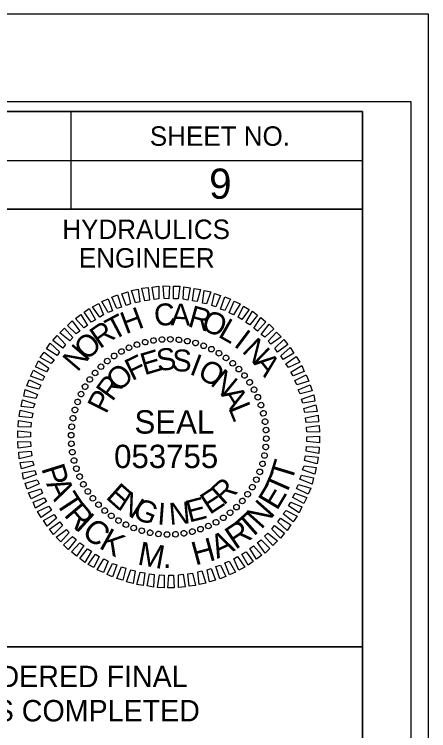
# Model space of a CAD drawing. Extents: x 1632687 to 1634895, y 1174336 to 1175436.
# Drawn here: x 1634264.8 to 1634371.3, y 1175251.7 to 1175435.8 of the extents above; entities that cross this region are included whole.
import ezdxf

# ---------------------------------------------------------------- set-up
doc = ezdxf.new("R2010")
doc.units = 0
for name, color, linetype in [('Sheet Data Field CELL', 7, 'Continuous'), ('Sheet PE Seal Cell', 7, 'Continuous'), ('Sheet Plot Border Inside CELL', 7, 'Continuous'), ('Sheet Plot Border Outside CELL', 7, 'Continuous'), ('Sheet Profile CELL', 7, 'Continuous'), ('Sheet Profile Grid Major CELL', 7, 'Continuous'), ('Sheet Sticker Exception Certification CELL', 7, 'Continuous')]:
    doc.layers.add(name, color=color, linetype=linetype)

msp = doc.modelspace()

# ---------------------------------------------------------------- linework, layer by layer
at = {"layer": 'Sheet PE Seal Cell'}
for p, q in [((1634302.73, 1175352.25), (1634302.73, 1175352.25)), ((1634304.93, 1175352.3), (1634304.93, 1175352.3)), ((1634296.28, 1175350.95), (1634296.28, 1175350.95)), ((1634298.38, 1175351.55), (1634298.38, 1175351.55)), ((1634300.58, 1175351.95), (1634300.58, 1175351.95)), ((1634307.13, 1175352.15), (1634307.13, 1175352.15)), ((1634309.28, 1175351.8), (1634309.28, 1175351.8)), ((1634311.38, 1175351.35), (1634311.38, 1175351.35)), ((1634313.48, 1175350.65), (1634313.48, 1175350.65)), ((1634292.33, 1175349.15), (1634292.33, 1175349.15)), ((1634294.28, 1175350.15), (1634294.28, 1175350.15)), ((1634315.48, 1175349.75), (1634315.48, 1175349.75)), ((1634317.43, 1175348.75), (1634317.43, 1175348.75)), ((1634288.68, 1175346.75), (1634288.68, 1175346.75)), ((1634290.43, 1175348), (1634290.43, 1175348)), ((1634319.23, 1175347.5), (1634319.23, 1175347.5)), ((1634287.03, 1175345.25), (1634287.03, 1175345.25)), ((1634320.98, 1175346.15), (1634320.98, 1175346.15)), ((1634285.53, 1175343.7), (1634285.53, 1175343.7)), ((1634322.53, 1175344.65), (1634322.53, 1175344.65)), ((1634284.18, 1175341.95), (1634284.18, 1175341.95)), ((1634324.03, 1175343), (1634324.03, 1175343)), ((1634325.28, 1175341.25), (1634325.28, 1175341.25)), ((1634282.93, 1175340.15), (1634282.93, 1175340.15)), ((1634281.93, 1175338.2), (1634281.93, 1175338.2)), ((1634326.43, 1175339.35), (1634326.43, 1175339.35)), ((1634281.03, 1175336.2), (1634281.03, 1175336.2)), ((1634327.43, 1175337.4), (1634327.43, 1175337.4)), ((1634280.33, 1175334.1), (1634280.33, 1175334.1)), ((1634328.23, 1175335.4), (1634328.23, 1175335.4)), ((1634279.88, 1175332), (1634279.88, 1175332)), ((1634328.83, 1175333.3), (1634328.83, 1175333.3)), ((1634329.23, 1175331.1), (1634329.23, 1175331.1)), ((1634279.53, 1175329.85), (1634279.53, 1175329.85)), ((1634329.53, 1175328.95), (1634329.53, 1175328.95)), ((1634279.38, 1175327.65), (1634279.38, 1175327.65)), ((1634304.48, 1175327.2), (1634304.48, 1175327.2)), ((1634329.58, 1175326.75), (1634329.58, 1175326.75)), ((1634279.43, 1175325.45), (1634279.43, 1175325.45)), ((1634279.73, 1175323.3), (1634279.73, 1175323.3)), ((1634329.43, 1175324.55), (1634329.43, 1175324.55)), ((1634280.13, 1175321.1), (1634280.13, 1175321.1)), ((1634329.08, 1175322.4), (1634329.08, 1175322.4)), ((1634328.63, 1175320.3), (1634328.63, 1175320.3)), ((1634280.73, 1175319), (1634280.73, 1175319)), ((1634327.93, 1175318.2), (1634327.93, 1175318.2)), ((1634281.53, 1175317), (1634281.53, 1175317)), ((1634327.03, 1175316.2), (1634327.03, 1175316.2)), ((1634282.53, 1175315.05), (1634282.53, 1175315.05)), ((1634326.03, 1175314.25), (1634326.03, 1175314.25)), ((1634283.68, 1175313.15), (1634283.68, 1175313.15)), ((1634324.78, 1175312.45), (1634324.78, 1175312.45)), ((1634284.93, 1175311.4), (1634284.93, 1175311.4)), ((1634323.43, 1175310.7), (1634323.43, 1175310.7)), ((1634286.43, 1175309.75), (1634286.43, 1175309.75)), ((1634287.98, 1175308.25), (1634287.98, 1175308.25)), ((1634321.93, 1175309.15), (1634321.93, 1175309.15)), ((1634289.73, 1175306.9), (1634289.73, 1175306.9)), ((1634318.53, 1175306.4), (1634318.53, 1175306.4)), ((1634320.28, 1175307.65), (1634320.28, 1175307.65)), ((1634291.53, 1175305.65), (1634291.53, 1175305.65)), ((1634293.48, 1175304.65), (1634293.48, 1175304.65)), ((1634316.63, 1175305.25), (1634316.63, 1175305.25)), ((1634295.48, 1175303.75), (1634295.48, 1175303.75)), ((1634297.58, 1175303.05), (1634297.58, 1175303.05)), ((1634299.68, 1175302.6), (1634299.68, 1175302.6)), ((1634310.58, 1175302.85), (1634310.58, 1175302.85)), ((1634312.68, 1175303.45), (1634312.68, 1175303.45)), ((1634314.68, 1175304.25), (1634314.68, 1175304.25)), ((1634301.83, 1175302.25), (1634301.83, 1175302.25)), ((1634304.03, 1175302.1), (1634304.03, 1175302.1)), ((1634306.23, 1175302.15), (1634306.23, 1175302.15)), ((1634308.38, 1175302.45), (1634308.38, 1175302.45))]:
    msp.add_line(p, q, dxfattribs=at)
for points in [[(1634295.98, 1175361.65), (1634294.93, 1175364.8), (1634296.63, 1175365.15), (1634297.03, 1175361.9)], [(1634298.38, 1175362.2), (1634297.58, 1175365.4), (1634299.23, 1175365.55), (1634299.58, 1175362.35)], [(1634300.78, 1175362.5), (1634300.23, 1175365.7), (1634301.93, 1175365.9), (1634301.98, 1175362.65)], [(1634303.28, 1175362.75), (1634303.03, 1175366), (1634304.68, 1175365.95), (1634304.48, 1175362.7)], [(1634305.68, 1175362.7), (1634305.68, 1175365.95), (1634307.33, 1175365.9), (1634306.88, 1175362.65)], [(1634308.18, 1175362.55), (1634308.38, 1175365.8), (1634310.03, 1175365.5), (1634309.38, 1175362.35)], [(1634310.58, 1175362.15), (1634311.03, 1175365.35), (1634312.68, 1175365.1), (1634311.78, 1175362)], [(1634291.13, 1175360.2), (1634289.83, 1175363.1), (1634291.33, 1175363.7), (1634292.38, 1175360.5)], [(1634293.58, 1175361), (1634292.43, 1175364), (1634293.98, 1175364.45), (1634294.63, 1175361.35)], [(1634313.13, 1175361.6), (1634313.63, 1175364.85), (1634315.33, 1175364.45), (1634314.18, 1175361.35)], [(1634315.53, 1175360.95), (1634316.28, 1175364.05), (1634317.83, 1175363.55), (1634316.58, 1175360.6)], [(1634286.78, 1175357.95), (1634284.93, 1175360.65), (1634286.48, 1175361.45), (1634287.73, 1175358.55)], [(1634288.93, 1175359.15), (1634287.33, 1175361.95), (1634288.88, 1175362.65), (1634290.03, 1175359.6)], [(1634317.78, 1175360.05), (1634318.93, 1175363.2), (1634320.33, 1175362.6), (1634318.93, 1175359.7)], [(1634320.03, 1175359.1), (1634321.28, 1175362.05), (1634322.83, 1175361.35), (1634321.13, 1175358.55)], [(1634284.58, 1175356.7), (1634282.73, 1175359.25), (1634284.03, 1175360.2), (1634285.68, 1175357.3)], [(1634322.33, 1175357.95), (1634323.68, 1175360.8), (1634325.18, 1175359.95), (1634323.28, 1175357.35)], [(1634282.68, 1175355.2), (1634280.53, 1175357.6), (1634281.88, 1175358.65), (1634283.63, 1175355.85)], [(1634324.28, 1175356.6), (1634326.03, 1175359.5), (1634327.33, 1175358.45), (1634325.38, 1175356)], [(1634326.33, 1175355.1), (1634328.18, 1175357.85), (1634329.48, 1175356.75), (1634327.28, 1175354.4)], [(1634280.68, 1175353.65), (1634278.48, 1175355.85), (1634279.68, 1175357.05), (1634281.63, 1175354.35)], [(1634328.23, 1175353.55), (1634330.28, 1175356.15), (1634331.48, 1175354.95), (1634329.18, 1175352.8)], [(1634279.03, 1175351.9), (1634276.48, 1175353.95), (1634277.73, 1175355.1), (1634279.83, 1175352.7)], [(1634330.03, 1175351.8), (1634332.18, 1175354.15), (1634333.38, 1175352.95), (1634330.78, 1175351)], [(1634277.28, 1175350), (1634274.68, 1175351.95), (1634275.78, 1175353.25), (1634277.98, 1175350.9)], [(1634331.78, 1175350), (1634334.08, 1175352.25), (1634335.13, 1175350.9), (1634332.48, 1175349)], [(1634275.78, 1175348.1), (1634273.08, 1175349.8), (1634274.03, 1175351.25), (1634276.43, 1175349.05)], [(1634274.28, 1175346.1), (1634271.48, 1175347.6), (1634272.48, 1175349), (1634275.08, 1175347)], [(1634333.28, 1175348.05), (1634335.73, 1175350.15), (1634336.68, 1175348.7), (1634333.88, 1175347.1)], [(1634273.08, 1175343.95), (1634270.23, 1175345.2), (1634270.98, 1175346.75), (1634273.68, 1175344.9)], [(1634334.58, 1175346), (1634337.23, 1175347.9), (1634338.18, 1175346.4), (1634335.28, 1175345)], [(1634335.88, 1175343.8), (1634338.68, 1175345.55), (1634339.33, 1175344), (1634336.48, 1175342.85)], [(1634272.08, 1175341.65), (1634268.98, 1175342.8), (1634269.73, 1175344.35), (1634272.58, 1175342.75)], [(1634336.88, 1175341.65), (1634339.83, 1175343.15), (1634340.48, 1175341.55), (1634337.38, 1175340.55)], [(1634271.08, 1175339.45), (1634267.98, 1175340.35), (1634268.63, 1175341.9), (1634271.63, 1175340.5)], [(1634337.78, 1175339.3), (1634340.83, 1175340.6), (1634341.38, 1175339.05), (1634338.28, 1175338.25)], [(1634270.33, 1175337.05), (1634267.23, 1175337.7), (1634267.58, 1175339.35), (1634270.73, 1175338.1)], [(1634338.58, 1175336.9), (1634341.78, 1175338.05), (1634342.08, 1175336.4), (1634338.93, 1175335.85)], [(1634269.68, 1175334.65), (1634266.58, 1175335.05), (1634266.93, 1175336.75), (1634270.08, 1175335.7)], [(1634269.28, 1175332.1), (1634266.08, 1175332.4), (1634266.28, 1175334.1), (1634269.53, 1175333.3)], [(1634339.18, 1175334.5), (1634342.33, 1175335.45), (1634342.63, 1175333.75), (1634339.48, 1175333.45)], [(1634339.63, 1175332.1), (1634342.88, 1175332.8), (1634343.03, 1175331.1), (1634339.83, 1175330.9)], [(1634269.03, 1175329.7), (1634265.78, 1175329.8), (1634265.88, 1175331.45), (1634269.13, 1175330.9)], [(1634268.98, 1175327.2), (1634265.73, 1175327.05), (1634265.73, 1175328.75), (1634268.98, 1175328.4)], [(1634339.93, 1175329.7), (1634343.18, 1175330.1), (1634343.28, 1175328.4), (1634340.03, 1175328.5)], [(1634339.98, 1175327.2), (1634343.23, 1175327.35), (1634343.23, 1175325.65), (1634339.98, 1175326)], [(1634269.03, 1175324.7), (1634265.78, 1175324.3), (1634265.68, 1175326), (1634268.93, 1175325.9)], [(1634339.93, 1175324.7), (1634343.18, 1175324.6), (1634343.08, 1175322.95), (1634339.83, 1175323.5)], [(1634269.33, 1175322.3), (1634266.08, 1175321.6), (1634265.93, 1175323.3), (1634269.13, 1175323.5)], [(1634269.78, 1175319.9), (1634266.63, 1175318.95), (1634266.33, 1175320.65), (1634269.48, 1175320.95)], [(1634339.68, 1175322.3), (1634342.88, 1175322), (1634342.68, 1175320.3), (1634339.43, 1175321.1)], [(1634339.28, 1175319.75), (1634342.38, 1175319.35), (1634342.03, 1175317.65), (1634338.88, 1175318.7)], [(1634270.38, 1175317.5), (1634267.18, 1175316.35), (1634266.88, 1175318), (1634270.03, 1175318.55)], [(1634338.63, 1175317.35), (1634341.73, 1175316.7), (1634341.38, 1175315.05), (1634338.23, 1175316.3)], [(1634271.18, 1175315.1), (1634268.13, 1175313.8), (1634267.58, 1175315.35), (1634270.68, 1175316.15)], [(1634272.08, 1175312.75), (1634269.13, 1175311.25), (1634268.48, 1175312.85), (1634271.58, 1175313.85)], [(1634337.88, 1175314.95), (1634340.98, 1175314.05), (1634340.33, 1175312.5), (1634337.33, 1175313.9)], [(1634336.88, 1175312.75), (1634339.98, 1175311.6), (1634339.23, 1175310.05), (1634336.38, 1175311.65)], [(1634273.08, 1175310.6), (1634270.28, 1175308.85), (1634269.63, 1175310.4), (1634272.48, 1175311.55)], [(1634335.88, 1175310.45), (1634338.73, 1175309.2), (1634337.98, 1175307.65), (1634335.28, 1175309.5)], [(1634274.38, 1175308.4), (1634271.73, 1175306.5), (1634270.78, 1175308), (1634273.68, 1175309.4)], [(1634334.68, 1175308.3), (1634337.48, 1175306.8), (1634336.48, 1175305.4), (1634333.88, 1175307.4)], [(1634275.68, 1175306.35), (1634273.23, 1175304.25), (1634272.28, 1175305.7), (1634275.08, 1175307.3)], [(1634333.18, 1175306.3), (1634335.88, 1175304.6), (1634334.93, 1175303.15), (1634332.53, 1175305.35)], [(1634277.18, 1175304.4), (1634274.88, 1175302.15), (1634273.83, 1175303.5), (1634276.48, 1175305.4)], [(1634331.68, 1175304.4), (1634334.28, 1175302.45), (1634333.18, 1175301.15), (1634330.98, 1175303.5)], [(1634278.93, 1175302.6), (1634276.78, 1175300.25), (1634275.58, 1175301.45), (1634278.18, 1175303.4)], [(1634280.73, 1175300.85), (1634278.68, 1175298.25), (1634277.48, 1175299.45), (1634279.78, 1175301.6)], [(1634328.28, 1175300.75), (1634330.48, 1175298.55), (1634329.28, 1175297.35), (1634327.33, 1175300.05)], [(1634329.93, 1175302.5), (1634332.48, 1175300.45), (1634331.23, 1175299.3), (1634329.13, 1175301.7)], [(1634282.63, 1175299.3), (1634280.78, 1175296.55), (1634279.48, 1175297.65), (1634281.68, 1175300)], [(1634326.28, 1175299.2), (1634328.43, 1175296.8), (1634327.08, 1175295.75), (1634325.33, 1175298.55)], [(1634284.68, 1175297.8), (1634282.93, 1175294.9), (1634281.63, 1175295.95), (1634283.58, 1175298.4)], [(1634286.63, 1175296.45), (1634285.28, 1175293.6), (1634283.78, 1175294.45), (1634285.68, 1175297.05)], [(1634324.38, 1175297.7), (1634326.23, 1175295.15), (1634324.93, 1175294.2), (1634323.28, 1175297.1)], [(1634288.93, 1175295.3), (1634287.68, 1175292.35), (1634286.13, 1175293.05), (1634287.83, 1175295.85)], [(1634320.03, 1175295.25), (1634321.63, 1175292.45), (1634320.08, 1175291.75), (1634318.93, 1175294.8)], [(1634322.18, 1175296.45), (1634324.03, 1175293.75), (1634322.48, 1175292.95), (1634321.23, 1175295.85)], [(1634291.18, 1175294.35), (1634290.03, 1175291.2), (1634288.63, 1175291.8), (1634290.03, 1175294.7)], [(1634293.43, 1175293.45), (1634292.68, 1175290.35), (1634291.13, 1175290.85), (1634292.38, 1175293.8)], [(1634315.38, 1175293.4), (1634316.53, 1175290.4), (1634314.98, 1175289.95), (1634314.33, 1175293.05)], [(1634317.83, 1175294.2), (1634319.13, 1175291.3), (1634317.63, 1175290.7), (1634316.58, 1175293.9)], [(1634295.83, 1175292.8), (1634295.33, 1175289.55), (1634293.63, 1175289.95), (1634294.78, 1175293.05)], [(1634298.38, 1175292.25), (1634297.93, 1175289.05), (1634296.28, 1175289.3), (1634297.18, 1175292.4)], [(1634300.78, 1175291.85), (1634300.58, 1175288.6), (1634298.93, 1175288.9), (1634299.58, 1175292.05)], [(1634303.28, 1175291.7), (1634303.28, 1175288.45), (1634301.63, 1175288.5), (1634302.08, 1175291.75)], [(1634305.68, 1175291.65), (1634305.93, 1175288.4), (1634304.28, 1175288.45), (1634304.48, 1175291.7)], [(1634308.18, 1175291.9), (1634308.73, 1175288.7), (1634307.03, 1175288.5), (1634306.98, 1175291.75)], [(1634310.58, 1175292.2), (1634311.38, 1175289), (1634309.73, 1175288.85), (1634309.38, 1175292.05)], [(1634312.98, 1175292.75), (1634314.03, 1175289.6), (1634312.33, 1175289.25), (1634311.93, 1175292.5)]]:
    msp.add_lwpolyline(points, close=True, dxfattribs=at)
for centre, major_axis in [((1634298.42, 1175351.53), (-0.174, 0.699)), ((1634300.56, 1175351.97), (-0.113, 0.711)), ((1634302.73, 1175352.22), (-0.05, 0.718)), ((1634304.92, 1175352.28), (0.013, 0.72)), ((1634307.11, 1175352.14), (0.075, 0.716)), ((1634309.27, 1175351.82), (0.137, 0.707)), ((1634294.28, 1175350.11), (-0.293, 0.658)), ((1634296.32, 1175350.91), (-0.234, 0.681)), ((1634311.4, 1175351.31), (0.198, 0.692)), ((1634313.47, 1175350.61), (0.258, 0.672)), ((1634315.48, 1175349.74), (0.316, 0.647)), ((1634290.46, 1175347.99), (-0.403, 0.597)), ((1634292.33, 1175349.14), (-0.349, 0.63)), ((1634317.4, 1175348.7), (0.371, 0.617)), ((1634288.7, 1175346.69), (-0.453, 0.56)), ((1634319.23, 1175347.49), (0.423, 0.582)), ((1634320.94, 1175346.13), (0.472, 0.543)), ((1634287.06, 1175345.24), (-0.5, 0.518)), ((1634322.53, 1175344.62), (0.518, 0.5)), ((1634285.56, 1175343.65), (-0.543, 0.472)), ((1634323.98, 1175342.98), (0.56, 0.453)), ((1634284.19, 1175341.94), (-0.582, 0.423)), ((1634325.28, 1175341.22), (0.597, 0.403)), ((1634282.99, 1175340.12), (-0.617, 0.371)), ((1634326.42, 1175339.36), (0.63, 0.349)), ((1634281.94, 1175338.19), (-0.647, 0.316)), ((1634327.4, 1175337.4), (0.658, 0.293)), ((1634281.07, 1175336.19), (-0.672, 0.258)), ((1634328.2, 1175335.37), (0.681, 0.234)), ((1634280.38, 1175334.11), (-0.692, 0.198)), ((1634328.82, 1175333.27), (0.699, 0.174)), ((1634279.87, 1175331.99), (-0.707, 0.137)), ((1634279.54, 1175329.82), (-0.716, 0.075)), ((1634329.26, 1175331.12), (0.711, 0.113)), ((1634279.41, 1175327.64), (-0.72, 0.013)), ((1634329.5, 1175328.95), (0.718, 0.05)), ((1634329.56, 1175326.76), (0.72, -0.013)), ((1634279.47, 1175325.45), (-0.718, -0.05)), ((1634329.43, 1175324.58), (0.716, -0.075)), ((1634279.71, 1175323.28), (-0.711, -0.113)), ((1634329.1, 1175322.41), (0.707, -0.137)), ((1634280.15, 1175321.13), (-0.699, -0.174)), ((1634328.59, 1175320.29), (0.692, -0.198)), ((1634280.77, 1175319.03), (-0.681, -0.234)), ((1634281.57, 1175317), (-0.658, -0.293)), ((1634327.9, 1175318.21), (0.672, -0.258)), ((1634282.55, 1175315.04), (-0.63, -0.349)), ((1634327.03, 1175316.21), (0.647, -0.316)), ((1634283.69, 1175313.18), (-0.597, -0.403)), ((1634325.98, 1175314.28), (0.617, -0.371)), ((1634284.99, 1175311.42), (-0.56, -0.453)), ((1634324.77, 1175312.46), (0.582, -0.423)), ((1634286.44, 1175309.78), (-0.518, -0.5)), ((1634321.91, 1175309.16), (0.5, -0.518)), ((1634323.41, 1175310.75), (0.543, -0.472)), ((1634288.03, 1175308.27), (-0.472, -0.543)), ((1634320.27, 1175307.71), (0.453, -0.56)), ((1634289.74, 1175306.91), (-0.423, -0.582)), ((1634291.57, 1175305.7), (-0.371, -0.617)), ((1634318.51, 1175306.41), (0.403, -0.597)), ((1634293.49, 1175304.66), (-0.316, -0.647)), ((1634295.5, 1175303.79), (-0.258, -0.672)), ((1634314.69, 1175304.29), (0.293, -0.658)), ((1634316.64, 1175305.26), (0.349, -0.63)), ((1634297.57, 1175303.09), (-0.198, -0.692)), ((1634299.7, 1175302.58), (-0.137, -0.707)), ((1634301.86, 1175302.26), (-0.075, -0.716)), ((1634304.05, 1175302.12), (-0.013, -0.72)), ((1634306.23, 1175302.18), (0.05, -0.718)), ((1634308.41, 1175302.43), (0.113, -0.711)), ((1634310.55, 1175302.86), (0.174, -0.699)), ((1634312.65, 1175303.49), (0.234, -0.681))]:
    msp.add_ellipse(centre, major_axis=major_axis, ratio=0.999708, dxfattribs=at)
at = {"layer": 'Sheet Plot Border Inside CELL'}
msp.add_lwpolyline([(1632700.31, 1174358.24), (1634366.81, 1174358.24), (1634366.81, 1175413.34), (1632700.31, 1175413.34)], close=True, dxfattribs=at)
at = {"layer": 'Sheet Plot Border Outside CELL'}
msp.add_lwpolyline([(1632687.31, 1174335.79), (1634371.31, 1174335.79), (1634371.31, 1175435.79), (1632687.31, 1175435.79)], close=True, dxfattribs=at)
at = {"layer": 'Sheet Profile CELL'}
for p, q in [((1634279.31, 1175410.74), (1634279.31, 1175385.74)), ((1634154.26, 1175398.24), (1634354.31, 1175398.24))]:
    msp.add_line(p, q, dxfattribs=at)
for points in [[(1634354.31, 1175410.79), (1632854.31, 1175410.79), (1632854.31, 1174360.79), (1634354.31, 1174360.79)], [(1634154.26, 1175410.79), (1634354.31, 1175410.79), (1634354.31, 1175385.74), (1634154.26, 1175385.74)], [(1634254.31, 1175385.74), (1634354.31, 1175385.74), (1634354.31, 1175273.24), (1634254.31, 1175273.24)]]:
    msp.add_lwpolyline(points, close=True, dxfattribs=at)
at = {"layer": 'Sheet Profile Grid Major CELL'}
msp.add_lwpolyline([(1634304.31, 1175249.74), (1634304.31, 1174910.79), (1634354.31, 1174910.79), (1634354.31, 1175260.79)], dxfattribs=at)
at = {"layer": 'Sheet Sticker Exception Certification CELL'}
for p, q in [((1634154.26, 1175273.24), (1634354.3, 1175273.24)), ((1634354.3, 1175273.22), (1634354.3, 1175249.72))]:
    msp.add_line(p, q, dxfattribs=at)

# ---------------------------------------------------------------- texts
at = {"layer": 'Sheet Data Field CELL'}
msp.add_text('9', height=7.75, rotation=360, dxfattribs=at).set_placement((1634314.88, 1175388.4))
at = {"layer": 'Sheet PE Seal Cell'}
for s, height, rotation, p in [('C', 5.64, 6.2199, (1634301.03, 1175355.55)), ('A', 5.64, 359.0203, (1634304.98, 1175355.85)), ('H', 5.64, 20.6195, (1634293.43, 1175353.55)), ('R', 5.64, 344.6211, (1634309.18, 1175355.65)), ('T', 5.64, 27.8198, (1634290.18, 1175351.9)), ('O', 5.64, 337.4212, (1634312.53, 1175354.9)), ('R', 5.64, 35.0205, (1634286.78, 1175349.7)), ('L', 5.64, 330.2209, (1634316.93, 1175353.05)), ('I', 5.64, 323.0201, (1634320.98, 1175350.65)), ('O', 5.64, 42.2217, (1634283.33, 1175346.6)), ('N', 5.64, 315.8189, (1634323.13, 1175349.1)), ('N', 5.64, 49.4235, (1634281.03, 1175343.7)), ('E', 5.64, 16.6111, (1634298.23, 1175343)), ('S', 5.64, 7.2556, (1634301.68, 1175344.05)), ('S', 5.64, 357.9004, (1634305.28, 1175344.1)), ('F', 5.64, 25.967, (1634295.03, 1175341.5)), ('I', 5.64, 339.1896, (1634309.58, 1175343.4)), ('O', 5.64, 329.8335, (1634311.58, 1175342.7)), ('A', 5.64, 308.6172, (1634326.08, 1175346.15)), ('O', 5.64, 44.6812, (1634291.73, 1175338.55)), ('N', 5.64, 320.4766, (1634314.93, 1175340.7)), ('R', 5.64, 54.0397, (1634289.98, 1175336.1)), ('P', 5.64, 63.3989, (1634288.38, 1175332.9)), ('A', 5.64, 301.7603, (1634317.78, 1175338.1)), ('L', 5.64, 292.4009, (1634319.73, 1175334.65)), ('SEAL', 5.998, 360, (1634295.69, 1175328.05)), ('T', 6, 72.9557, (1634336.09, 1175315.32)), ('P', 6, 287.3534, (1634271.69, 1175319.14)), ('T', 6, 66.1555, (1634334.46, 1175311.66)), ('A', 6, 294.4627, (1634272.94, 1175315.15)), ('R', 5.64, 42.4814, (1634318.58, 1175309.45)), ('E', 5.64, 318.2769, (1634288.08, 1175311.55)), ('E', 5.64, 33.1241, (1634315.03, 1175307.1)), ('E', 6, 59.0461, (1634332.31, 1175308.07)), ('T', 6, 303.303, (1634275.17, 1175310.44)), ('N', 5.64, 327.634, (1634291.08, 1175308.85)), ('R', 6, 310.1033, (1634277.36, 1175307.09)), ('G', 5.64, 336.9902, (1634294.88, 1175306.6)), ('I', 5.64, 355.7012, (1634301.43, 1175304.7)), ('N', 5.64, 5.0564, (1634304.78, 1175304.55)), ('E', 5.64, 14.4118, (1634309.73, 1175305.15)), ('N', 6, 48.3203, (1634328.26, 1175303.23)), ('T', 6, 41.5201, (1634325.26, 1175300.58)), ('I', 6, 317.5835, (1634280.21, 1175303.73)), ('C', 6, 321.3855, (1634281.82, 1175302.17)), ('R', 6, 34.0398, (1634321.62, 1175298.1)), ('K', 6, 330.9676, (1634286.3, 1175298.75)), ('A', 6, 25.1995, (1634316.94, 1175295.82)), ('H', 6, 15.2155, (1634311.31, 1175294.13)), ('M', 6, 349.4519, (1634296.26, 1175294.45)), ('.', 6, 0.9814, (1634302.97, 1175293.47))]:
    msp.add_text(s, height=height, rotation=rotation, dxfattribs=at).set_placement(p)
msp.add_text('053755', height=5.998, dxfattribs=at).set_placement((1634290.45, 1175319.19))
at = {"layer": 'Sheet Profile CELL'}
for s, p in [('SHEET NO.', (1634299.63, 1175402)), ('HYDRAULICS', (1634277.13, 1175378.05)), ('ENGINEER', (1634281.38, 1175370.7))]:
    msp.add_text(s, height=5, rotation=360, dxfattribs=at).set_placement(p)
at = {"layer": 'Sheet Sticker Exception Certification CELL'}
for s, p in [('DOCUMENT NOT CONSIDERED FINAL', (1634175.33, 1175262.89)), ('UNLESS ALL SIGNATURES COMPLETED', (1634170.26, 1175254.09))]:
    msp.add_text(s, height=5.5, rotation=360, dxfattribs=at).set_placement(p)

doc.saveas('drawing.dxf')
